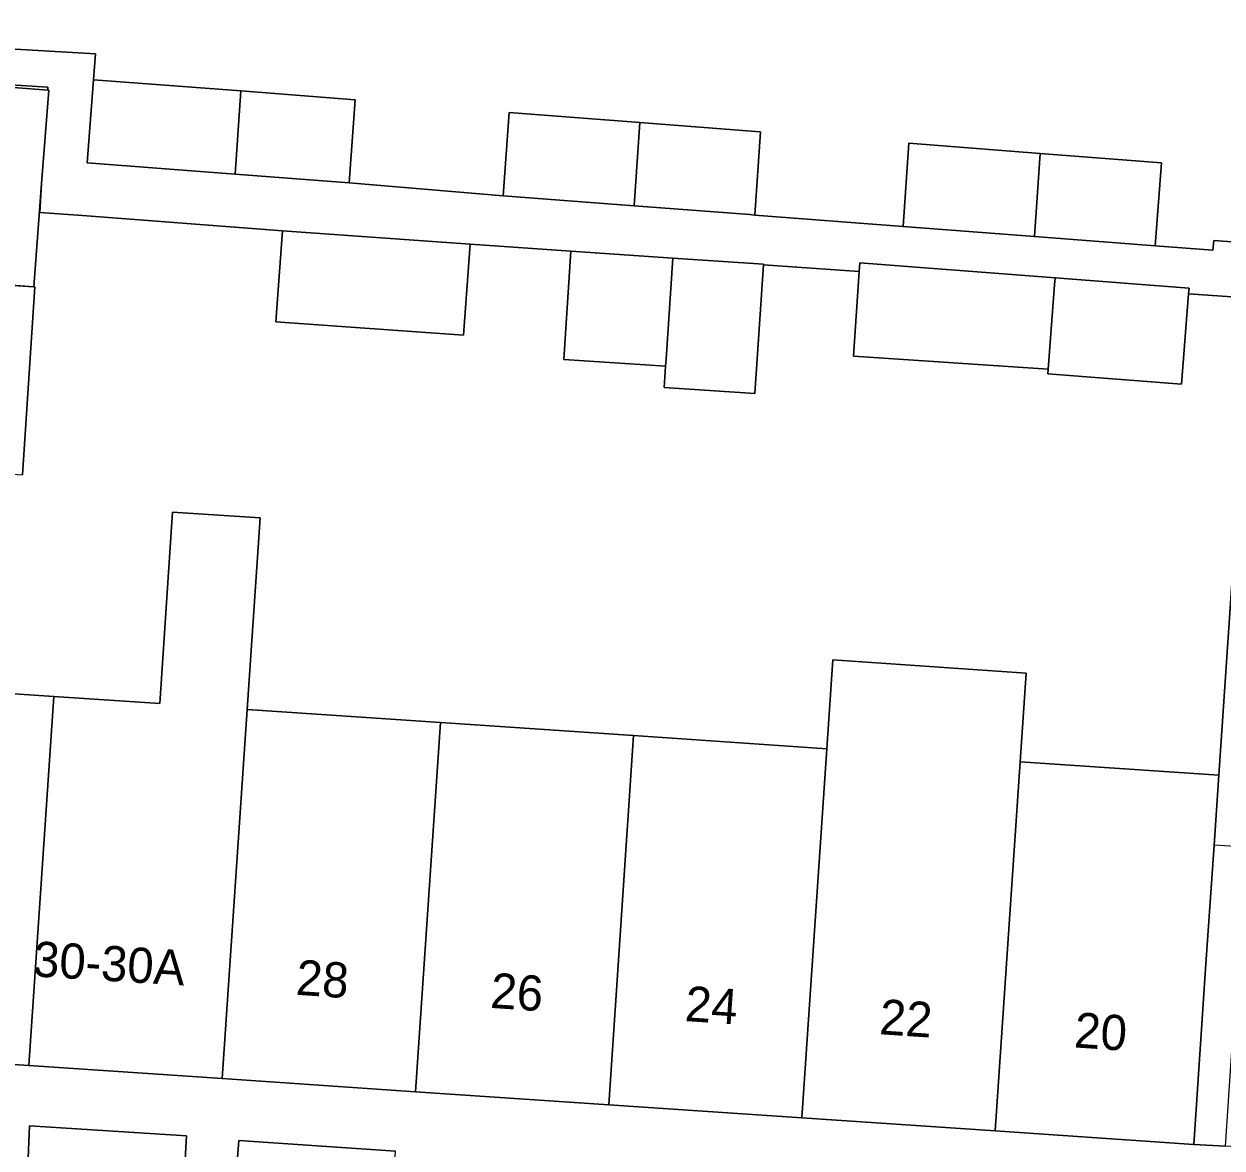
# Model space of a CAD drawing. Extents: x 159960 to 160866, y 382700 to 383354.
# Drawn here: x 160662.11 to 160696.13, y 382890.94 to 382922.88 of the extents above; entities that cross this region are included whole.
import ezdxf

# ---------------------------------------------------------------- set-up
doc = ezdxf.new("R2010")
doc.units = 0
for name, color, linetype in [('IMGEO_Erf', 7, 'Continuous'), ('IMGEO_Groenvoorziening', 7, 'Continuous'), ('IMGEO_Pand', 7, 'Continuous'), ('IMGEO_Pand_nummerreeks', 7, 'Continuous'), ('IMGEO_Pand_overbouw', 7, 'Continuous'), ('IMGEO_Parkeervlak_open', 7, 'Continuous'), ('IMGEO_Voetpad_open', 7, 'Continuous')]:
    doc.layers.add(name, color=color, linetype=linetype)

msp = doc.modelspace()

# ---------------------------------------------------------------- linework, layer by layer
at = {"layer": 'IMGEO_Erf'}
for points in [[(160649.461, 382922.877), (160664.143, 382922.031), (160664.086, 382921.294), (160668.261, 382920.973), (160671.508, 382920.723), (160671.34, 382918.363), (160675.717, 382917.997), (160675.885, 382920.359), (160679.593, 382920.074), (160682.877, 382919.821), (160683.021, 382919.81), (160682.86, 382917.448), (160687.073, 382917.124), (160687.234, 382919.486), (160690.968, 382919.2), (160694.411, 382918.935), (160694.23, 382916.573), (160695.87, 382916.447), (160695.892, 382916.728), (160698.086, 382916.56)], [(160659.618, 382921.242), (160662.784, 382920.999), (160662.789, 382921.078), (160644.513, 382922.238)], [(160657.47, 382904.142), (160662.957, 382903.771), (160665.961, 382903.568), (160666.328, 382909.009), (160668.813, 382908.841), (160668.445, 382903.4), (160673.932, 382903.028), (160679.42, 382902.657), (160684.907, 382902.285), (160685.078, 382904.808), (160690.566, 382904.437), (160690.395, 382901.914), (160696.034, 382901.532), (160696.951, 382915.091), (160695.177, 382915.211), (160694.98, 382912.64), (160691.179, 382912.932), (160691.189, 382913.067), (160685.661, 382913.442), (160685.824, 382915.843), (160683.104, 382916.038), (160682.862, 382912.376), (160680.288, 382912.546), (160680.328, 382913.157), (160677.435, 382913.347), (160677.637, 382916.418), (160674.774, 382916.621), (160674.589, 382914.033), (160669.26, 382914.412), (160669.445, 382917), (160663.765, 382917.436), (160662.555, 382917.516), (160662.609, 382918.34), (160662.384, 382915.406), (160662.416, 382915.404), (160662.065, 382910.069)], [(160658.868, 382915.637), (160662.375, 382915.407), (160659.189, 382915.651)]]:
    msp.add_lwpolyline(points, dxfattribs=at)
at = {"layer": 'IMGEO_Groenvoorziening'}
msp.add_lwpolyline([(160672.537, 382889.036), (160672.661, 382890.85), (160668.204, 382891.158), (160668.062, 382889.342)], close=True, dxfattribs=at)
at = {"layer": 'IMGEO_Pand'}
for points in [[(160662.609, 382918.34), (160662.813, 382920.997), (160662.784, 382920.999), (160659.618, 382921.242), (160659.189, 382915.651), (160662.375, 382915.407), (160662.384, 382915.406)], [(160668.261, 382920.973), (160664.086, 382921.294), (160663.905, 382918.935), (160668.102, 382918.612)], [(160668.261, 382920.973), (160668.102, 382918.612), (160671.34, 382918.363), (160671.508, 382920.723)], [(160679.593, 382920.074), (160675.885, 382920.359), (160675.717, 382917.997), (160679.431, 382917.712)], [(160679.593, 382920.074), (160679.431, 382917.712), (160682.716, 382917.459), (160682.86, 382917.448), (160683.021, 382919.81), (160682.877, 382919.821)], [(160690.968, 382919.2), (160687.234, 382919.486), (160687.073, 382917.124), (160690.806, 382916.837)], [(160690.968, 382919.2), (160690.806, 382916.837), (160694.23, 382916.573), (160694.411, 382918.935)], [(160674.774, 382916.621), (160669.445, 382917), (160669.26, 382914.412), (160674.589, 382914.033)], [(160680.53, 382916.225), (160677.637, 382916.418), (160677.435, 382913.347), (160680.328, 382913.157), (160680.341, 382913.349)], [(160683.104, 382916.038), (160683.105, 382916.055), (160680.53, 382916.225), (160680.341, 382913.349), (160680.328, 382913.157), (160680.288, 382912.546), (160682.862, 382912.376)], [(160691.374, 382915.468), (160691.389, 382915.667), (160685.841, 382916.093), (160685.824, 382915.843), (160685.661, 382913.442), (160691.189, 382913.067)], [(160662.416, 382915.404), (160662.384, 382915.406), (160662.375, 382915.407), (160658.868, 382915.637), (160658.517, 382910.302), (160662.065, 382910.069)], [(160695.177, 382915.211), (160695.19, 382915.375), (160691.389, 382915.667), (160691.374, 382915.468), (160691.189, 382913.067), (160691.179, 382912.932), (160694.98, 382912.64)], [(160668.445, 382903.4), (160668.813, 382908.841), (160666.328, 382909.009), (160665.961, 382903.568), (160662.957, 382903.771), (160662.248, 382893.285), (160667.736, 382892.913)], [(160690.395, 382901.914), (160690.566, 382904.437), (160685.078, 382904.808), (160684.907, 382902.285), (160684.198, 382891.799), (160689.686, 382891.428)], [(160656.761, 382893.656), (160662.248, 382893.285), (160662.957, 382903.771), (160657.47, 382904.142)], [(160673.223, 382892.542), (160673.932, 382903.028), (160668.445, 382903.4), (160667.736, 382892.913)], [(160679.42, 382902.657), (160673.932, 382903.028), (160673.223, 382892.542), (160678.711, 382892.171)], [(160679.42, 382902.657), (160678.711, 382892.171), (160684.198, 382891.799), (160684.907, 382902.285)], [(160690.395, 382901.914), (160689.686, 382891.428), (160695.323, 382891.046), (160695.661, 382896.035), (160695.9, 382899.549), (160696.034, 382901.532)]]:
    msp.add_lwpolyline(points, close=True, dxfattribs=at)
at = {"layer": 'IMGEO_Pand_overbouw'}
msp.add_lwpolyline([(160695.9, 382899.549), (160695.661, 382896.035), (160695.323, 382891.046), (160696.222, 382890.997), (160696.56, 382895.986), (160696.798, 382899.488)], close=True, dxfattribs=at)
at = {"layer": 'IMGEO_Parkeervlak_open'}
msp.add_lwpolyline([(160666.619, 382889.441), (160666.722, 382891.292), (160662.264, 382891.576), (160662.19, 382889.744)], close=True, dxfattribs=at)
at = {"layer": 'IMGEO_Voetpad_open'}
for points in [[(160698.086, 382916.56), (160695.892, 382916.728), (160695.87, 382916.447), (160694.23, 382916.573), (160690.806, 382916.837), (160687.073, 382917.124), (160682.86, 382917.448), (160682.716, 382917.459), (160679.431, 382917.712), (160675.717, 382917.997), (160671.34, 382918.363), (160668.102, 382918.612), (160663.905, 382918.935), (160664.086, 382921.294), (160664.143, 382922.031), (160649.461, 382922.877)], [(160644.513, 382922.238), (160662.789, 382921.078), (160662.784, 382920.999), (160662.813, 382920.997), (160662.609, 382918.34), (160662.555, 382917.516), (160663.765, 382917.436), (160669.445, 382917), (160674.774, 382916.621), (160677.637, 382916.418), (160680.53, 382916.225), (160683.105, 382916.055), (160683.104, 382916.038), (160685.824, 382915.843), (160685.841, 382916.093), (160691.389, 382915.667), (160695.19, 382915.375), (160695.177, 382915.211), (160696.951, 382915.091), (160696.034, 382901.532), (160695.9, 382899.549), (160695.661, 382896.035), (160695.323, 382891.046), (160696.222, 382890.997)], [(160723.863, 382889.125), (160718.365, 382889.497), (160712.866, 382889.87), (160707.368, 382890.242), (160701.869, 382890.615), (160696.222, 382890.997), (160695.323, 382891.046), (160689.686, 382891.428), (160684.198, 382891.799), (160678.711, 382892.171), (160673.223, 382892.542), (160667.736, 382892.913), (160662.248, 382893.285), (160656.761, 382893.656)], [(160662.19, 382889.744), (160662.264, 382891.576), (160666.722, 382891.292), (160666.619, 382889.441)], [(160668.062, 382889.342), (160668.204, 382891.158), (160672.661, 382890.85)]]:
    msp.add_lwpolyline(points, dxfattribs=at)

# ---------------------------------------------------------------- texts
at = {"layer": 'IMGEO_Pand_nummerreeks'}
for s, rotation, p in [('30-30A', 356.4935, (160662.346, 382895.821)), ('28', 356.1273, (160669.81, 382895.298)), ('26', 356.1273, (160675.332, 382894.925)), ('24', 356.1273, (160680.857, 382894.551)), ('22', 356.1268, (160686.379, 382894.177)), ('20', 356.1273, (160691.909, 382893.802))]:
    msp.add_text(s, height=1, rotation=rotation, dxfattribs=at).set_placement(p)

doc.saveas('drawing.dxf')
